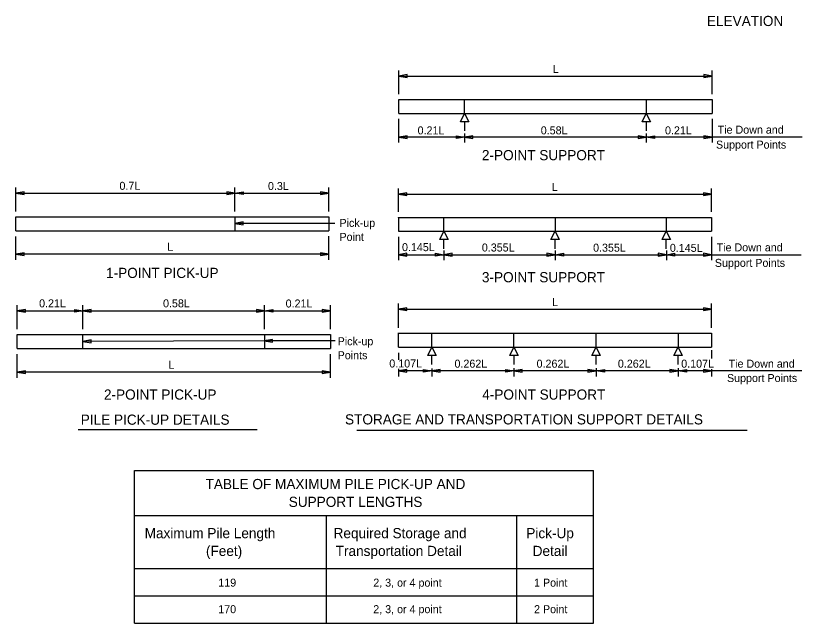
# Model space of a CAD drawing. Extents: x 120519.5 to 120592, y 120568.7 to 120603.1.
# Drawn here: x 120521.5 to 120541.31, y 120572.3 to 120587.6 of the extents above; entities that cross this region are included whole.
import ezdxf

# ---------------------------------------------------------------- set-up
doc = ezdxf.new("R2010")
doc.units = 0
for name, color, linetype in [('Dimension', 7, 'Continuous'), ('PileConc', 7, 'Continuous'), ('TextStructures', 7, 'Continuous')]:
    doc.layers.add(name, color=color, linetype=linetype)

msp = doc.modelspace()

# ---------------------------------------------------------------- linework, layer by layer
at = {"layer": 'Dimension'}
for p, q in [((120531.151, 120585.633), (120531.151, 120586.226)), ((120539.041, 120585.633), (120539.041, 120586.226)), ((120531.151, 120586.086), (120539.041, 120586.086)), ((120531.151, 120584.408), (120531.151, 120585.004)), ((120539.041, 120585.004), (120539.041, 120584.408)), ((120532.81, 120584.704), (120532.81, 120584.936)), ((120537.386, 120584.704), (120537.386, 120584.936)), ((120541.313, 120584.548), (120531.151, 120584.548)), ((120532.808, 120584.638), (120532.808, 120584.408)), ((120537.385, 120584.636), (120537.385, 120584.408)), ((120521.501, 120582.678), (120521.501, 120583.277)), ((120527.023, 120582.678), (120527.023, 120583.277)), ((120529.39, 120582.678), (120529.39, 120583.277)), ((120531.141, 120582.664), (120531.141, 120583.252)), ((120539.03, 120582.664), (120539.03, 120583.252)), ((120521.501, 120583.137), (120529.39, 120583.137)), ((120531.141, 120583.112), (120539.03, 120583.112)), ((120529.54, 120582.376), (120527.023, 120582.376)), ((120531.141, 120582.524), (120531.141, 120582.532)), ((120532.283, 120582.524), (120532.283, 120582.527)), ((120535.085, 120582.524), (120535.085, 120582.531)), ((120521.501, 120581.46), (120521.501, 120582.048)), ((120529.39, 120581.46), (120529.39, 120582.05)), ((120531.141, 120582.036), (120531.141, 120581.447)), ((120532.286, 120581.736), (120532.286, 120581.967)), ((120535.086, 120581.736), (120535.086, 120581.967)), ((120537.888, 120581.736), (120537.888, 120581.967)), ((120539.03, 120582.036), (120539.03, 120581.447)), ((120529.39, 120581.6), (120521.501, 120581.6)), ((120531.141, 120581.587), (120541.285, 120581.587)), ((120532.285, 120581.691), (120532.285, 120581.447)), ((120535.088, 120581.691), (120535.088, 120581.447)), ((120537.89, 120581.691), (120537.89, 120581.447)), ((120521.538, 120579.713), (120521.538, 120580.313)), ((120523.195, 120579.713), (120523.195, 120580.313)), ((120527.771, 120579.713), (120527.771, 120580.313)), ((120529.428, 120579.713), (120529.428, 120580.313)), ((120531.141, 120579.747), (120531.141, 120580.354)), ((120531.141, 120580.214), (120539.03, 120580.214)), ((120539.03, 120579.747), (120539.03, 120580.354)), ((120521.538, 120580.173), (120529.428, 120580.173)), ((120531.141, 120579.607), (120531.141, 120579.615)), ((120532.283, 120579.607), (120532.283, 120579.61)), ((120535.085, 120579.607), (120535.085, 120579.613)), ((120527.761, 120579.42), (120523.195, 120579.403)), ((120529.546, 120579.42), (120527.761, 120579.42)), ((120521.538, 120578.489), (120521.538, 120579.085)), ((120529.428, 120578.489), (120529.428, 120579.085)), ((120531.141, 120579.118), (120531.141, 120578.938)), ((120531.986, 120578.818), (120531.986, 120579.05)), ((120534.053, 120578.818), (120534.053, 120579.05)), ((120536.12, 120578.818), (120536.12, 120579.05)), ((120538.188, 120578.818), (120538.188, 120579.05)), ((120539.03, 120579.181), (120539.03, 120578.971)), ((120529.428, 120578.629), (120521.538, 120578.629)), ((120531.141, 120578.714), (120531.141, 120578.522)), ((120541.298, 120578.662), (120531.141, 120578.662)), ((120531.985, 120578.717), (120531.985, 120578.522)), ((120534.051, 120578.73), (120534.051, 120578.522)), ((120536.118, 120578.73), (120536.118, 120578.522)), ((120538.185, 120578.728), (120538.185, 120578.522)), ((120539.03, 120578.7), (120539.03, 120578.522)), ((120531.985, 120578.587), (120531.985, 120578.522)), ((120536.121, 120578.522), (120536.121, 120578.522)), ((120527.583, 120577.177), (120523.078, 120577.177)), ((120530.09, 120577.17), (120539.927, 120577.17)), ((120524.495, 120576.156), (120536.056, 120576.156)), ((120524.495, 120572.305), (120524.495, 120576.156)), ((120536.056, 120572.305), (120536.056, 120576.156)), ((120524.495, 120575.02), (120536.056, 120575.02)), ((120529.328, 120572.305), (120529.328, 120575.02)), ((120534.123, 120572.305), (120534.123, 120575.02)), ((120524.495, 120573.684), (120536.056, 120573.684)), ((120524.495, 120572.995), (120536.056, 120572.995)), ((120524.495, 120572.305), (120536.056, 120572.305))]:
    msp.add_line(p, q, dxfattribs=at)
for points in [[(120531.151, 120586.086), (120531.36, 120586.051), (120531.36, 120586.122)], [(120539.041, 120586.086), (120538.833, 120586.122), (120538.833, 120586.051)], [(120532.808, 120585.144), (120532.913, 120584.936), (120532.703, 120584.936)], [(120537.385, 120585.144), (120537.49, 120584.936), (120537.28, 120584.936)], [(120531.151, 120584.548), (120531.36, 120584.513), (120531.36, 120584.584)], [(120532.808, 120584.548), (120532.6, 120584.513), (120532.6, 120584.584)], [(120532.808, 120584.548), (120533.016, 120584.513), (120533.016, 120584.584)], [(120537.385, 120584.548), (120537.176, 120584.584), (120537.176, 120584.513)], [(120537.385, 120584.548), (120537.593, 120584.584), (120537.593, 120584.513)], [(120539.041, 120584.548), (120538.833, 120584.584), (120538.833, 120584.513)], [(120521.501, 120583.137), (120521.71, 120583.102), (120521.71, 120583.173)], [(120527.023, 120583.137), (120526.815, 120583.173), (120526.815, 120583.102)], [(120527.023, 120583.137), (120527.231, 120583.173), (120527.231, 120583.102)], [(120529.39, 120583.137), (120529.182, 120583.173), (120529.182, 120583.102)], [(120531.141, 120583.112), (120531.35, 120583.077), (120531.35, 120583.148)], [(120539.03, 120583.112), (120538.821, 120583.148), (120538.821, 120583.077)], [(120527.023, 120582.376), (120527.231, 120582.341), (120527.231, 120582.411)], [(120532.285, 120582.176), (120532.39, 120581.967), (120532.18, 120581.967)], [(120535.085, 120582.176), (120535.19, 120581.967), (120534.98, 120581.967)], [(120537.886, 120582.176), (120537.991, 120581.967), (120537.781, 120581.967)], [(120521.501, 120581.6), (120521.71, 120581.564), (120521.71, 120581.635)], [(120529.39, 120581.6), (120529.182, 120581.635), (120529.182, 120581.564)], [(120531.141, 120581.587), (120531.35, 120581.552), (120531.35, 120581.623)], [(120532.285, 120581.587), (120532.076, 120581.552), (120532.076, 120581.623)], [(120532.285, 120581.587), (120532.493, 120581.552), (120532.493, 120581.623)], [(120535.088, 120581.587), (120534.88, 120581.623), (120534.88, 120581.552)], [(120535.088, 120581.587), (120535.296, 120581.623), (120535.296, 120581.552)], [(120537.89, 120581.587), (120537.681, 120581.623), (120537.681, 120581.552)], [(120537.89, 120581.587), (120538.098, 120581.623), (120538.098, 120581.552)], [(120539.03, 120581.587), (120538.821, 120581.623), (120538.821, 120581.552)], [(120521.538, 120580.173), (120521.746, 120580.138), (120521.746, 120580.208)], [(120523.195, 120580.173), (120522.987, 120580.138), (120522.987, 120580.208)], [(120523.195, 120580.173), (120523.403, 120580.138), (120523.403, 120580.208)], [(120527.771, 120580.173), (120527.563, 120580.208), (120527.563, 120580.138)], [(120527.771, 120580.173), (120527.98, 120580.208), (120527.98, 120580.138)], [(120529.428, 120580.173), (120529.22, 120580.208), (120529.22, 120580.138)], [(120531.141, 120580.214), (120531.35, 120580.178), (120531.35, 120580.249)], [(120539.03, 120580.214), (120538.821, 120580.249), (120538.821, 120580.178)], [(120523.195, 120579.403), (120523.403, 120579.369), (120523.403, 120579.439)], [(120527.761, 120579.42), (120527.97, 120579.385), (120527.97, 120579.455)], [(120531.985, 120579.258), (120532.09, 120579.05), (120531.88, 120579.05)], [(120534.051, 120579.258), (120534.156, 120579.05), (120533.946, 120579.05)], [(120536.118, 120579.258), (120536.223, 120579.05), (120536.013, 120579.05)], [(120538.186, 120579.258), (120538.291, 120579.05), (120538.081, 120579.05)], [(120521.538, 120578.629), (120521.746, 120578.594), (120521.746, 120578.665)], [(120529.428, 120578.629), (120529.22, 120578.665), (120529.22, 120578.594)], [(120531.141, 120578.662), (120531.35, 120578.626), (120531.35, 120578.697)], [(120531.985, 120578.662), (120531.776, 120578.626), (120531.776, 120578.697)], [(120531.985, 120578.662), (120532.193, 120578.626), (120532.193, 120578.697)], [(120534.051, 120578.662), (120533.843, 120578.626), (120533.843, 120578.697)], [(120534.051, 120578.662), (120534.26, 120578.626), (120534.26, 120578.697)], [(120536.118, 120578.662), (120535.91, 120578.697), (120535.91, 120578.626)], [(120536.125, 120578.662), (120536.333, 120578.697), (120536.333, 120578.626)], [(120538.185, 120578.662), (120537.976, 120578.697), (120537.976, 120578.626)], [(120538.185, 120578.662), (120538.393, 120578.697), (120538.393, 120578.626)], [(120539.03, 120578.662), (120538.821, 120578.697), (120538.821, 120578.626)]]:
    msp.add_lwpolyline(points, close=True, dxfattribs=at)
at = {"layer": 'PileConc'}
for p, q in [((120531.151, 120585.493), (120539.041, 120585.493)), ((120531.151, 120585.144), (120531.151, 120585.493)), ((120532.808, 120585.144), (120532.808, 120585.493)), ((120537.385, 120585.493), (120537.385, 120585.144)), ((120539.041, 120585.493), (120539.041, 120585.144)), ((120531.151, 120585.144), (120539.041, 120585.144)), ((120521.501, 120582.538), (120529.39, 120582.538)), ((120521.501, 120582.19), (120521.501, 120582.538)), ((120527.023, 120582.538), (120527.023, 120582.19)), ((120529.39, 120582.538), (120529.39, 120582.19)), ((120531.141, 120582.524), (120539.03, 120582.524)), ((120531.141, 120582.524), (120531.141, 120582.176)), ((120532.283, 120582.176), (120532.283, 120582.524)), ((120532.285, 120582.176), (120532.285, 120582.524)), ((120535.085, 120582.524), (120535.085, 120582.176)), ((120535.233, 120582.524), (120539.03, 120582.524)), ((120537.886, 120582.524), (120537.886, 120582.176)), ((120539.03, 120582.524), (120539.03, 120582.176)), ((120521.501, 120582.19), (120529.39, 120582.19)), ((120531.141, 120582.176), (120539.03, 120582.176)), ((120531.141, 120579.607), (120539.03, 120579.607)), ((120531.141, 120579.258), (120531.141, 120579.607)), ((120531.985, 120579.258), (120531.985, 120579.607)), ((120534.051, 120579.258), (120534.051, 120579.607)), ((120535.233, 120579.607), (120539.03, 120579.607)), ((120536.118, 120579.258), (120536.118, 120579.607)), ((120538.186, 120579.607), (120538.186, 120579.258)), ((120539.03, 120579.607), (120539.03, 120579.258)), ((120521.538, 120579.573), (120529.428, 120579.573)), ((120521.538, 120579.225), (120521.538, 120579.573)), ((120523.195, 120579.225), (120523.195, 120579.573)), ((120527.771, 120579.573), (120527.771, 120579.225)), ((120529.428, 120579.573), (120529.428, 120579.225)), ((120521.538, 120579.225), (120529.428, 120579.225)), ((120531.141, 120579.258), (120539.03, 120579.258))]:
    msp.add_line(p, q, dxfattribs=at)

# ---------------------------------------------------------------- texts
at = {"layer": 'Dimension'}
for s, height, p in [('Pick-up ', 0.2016, (120529.656, 120582.286)), ('Point', 0.2016, (120529.656, 120581.934)), ('Pick-up ', 0.2016, (120529.61, 120579.306)), ('Points', 0.2016, (120529.61, 120578.954)), ('TABLE OF MAXIMUM PILE PICK-UP AND', 0.256, (120526.283, 120575.683)), ('SUPPORT LENGTHS', 0.256, (120528.378, 120575.235)), ('Maximum Pile Length', 0.256, (120524.749, 120574.447)), ('Required Storage and', 0.256, (120529.508, 120574.447)), ('Pick-Up', 0.256, (120534.362, 120574.447)), ('(Feet)', 0.256, (120526.293, 120573.999)), ('Transportation Detail  ', 0.256, (120529.561, 120573.999)), ('Detail', 0.256, (120534.523, 120573.999))]:
    msp.add_text(s, height=height, dxfattribs=at).set_placement(p)
at = {"layer": 'TextStructures'}
for s, height, p in [('ELEVATION', 0.256, (120538.912, 120587.345)), ('L', 0.202, (120535.031, 120586.163)), ('0.21L', 0.2016, (120531.624, 120584.616)), ('0.58L', 0.2016, (120534.726, 120584.617)), ('0.21L', 0.2016, (120537.856, 120584.617)), ('Tie Down and', 0.2016, (120539.182, 120584.634)), ('Support Points', 0.2016, (120539.14, 120584.258)), ('2-POINT SUPPORT', 0.256, (120533.244, 120583.966)), ('0.7L', 0.2016, (120524.114, 120583.221)), ('0.3L', 0.2016, (120527.855, 120583.215)), ('L', 0.202, (120535.001, 120583.192)), ('L', 0.202, (120525.318, 120581.684)), ('0.145L', 0.2016, (120531.231, 120581.676)), ('0.355L', 0.2016, (120533.242, 120581.667)), ('0.355L', 0.2016, (120536.044, 120581.662)), ('0.145L', 0.2016, (120537.978, 120581.658)), ('Tie Down and', 0.2016, (120539.156, 120581.67)), ('Support Points', 0.2016, (120539.111, 120581.28)), ('1-POINT PICK-UP', 0.256, (120523.777, 120581)), ('3-POINT SUPPORT', 0.256, (120533.244, 120580.892)), ('0.21L', 0.2016, (120522.09, 120580.261)), ('0.58L', 0.2016, (120525.212, 120580.261)), ('0.21L', 0.2016, (120528.3, 120580.257)), ('L', 0.202, (120535.01, 120580.293)), ('L', 0.202, (120525.349, 120578.713)), ('0.107L', 0.2016, (120530.911, 120578.746)), ('0.262L', 0.2016, (120532.553, 120578.741)), ('0.262L', 0.2016, (120534.621, 120578.741)), ('0.262L', 0.2016, (120536.669, 120578.741)), ('0.107L', 0.2016, (120538.264, 120578.741)), ('Tie Down and', 0.2016, (120539.458, 120578.742)), ('Support Points', 0.2016, (120539.417, 120578.38)), ('2-POINT PICK-UP', 0.256, (120523.724, 120577.937)), ('4-POINT SUPPORT', 0.256, (120533.252, 120577.937)), ('PILE PICK-UP DETAILS', 0.256, (120523.139, 120577.304)), ('STORAGE AND TRANSPORTATION SUPPORT DETAILS', 0.256, (120529.796, 120577.312)), ('119', 0.2016, (120526.604, 120573.227)), ('2, 3, or 4 point', 0.2016, (120530.507, 120573.227)), ('1 Point', 0.2016, (120534.557, 120573.227)), ('170', 0.2016, (120526.603, 120572.559)), ('2, 3, or 4 point', 0.2016, (120530.507, 120572.559)), ('2 Point', 0.2016, (120534.557, 120572.559))]:
    msp.add_text(s, height=height, dxfattribs=at).set_placement(p)

doc.saveas('drawing.dxf')
